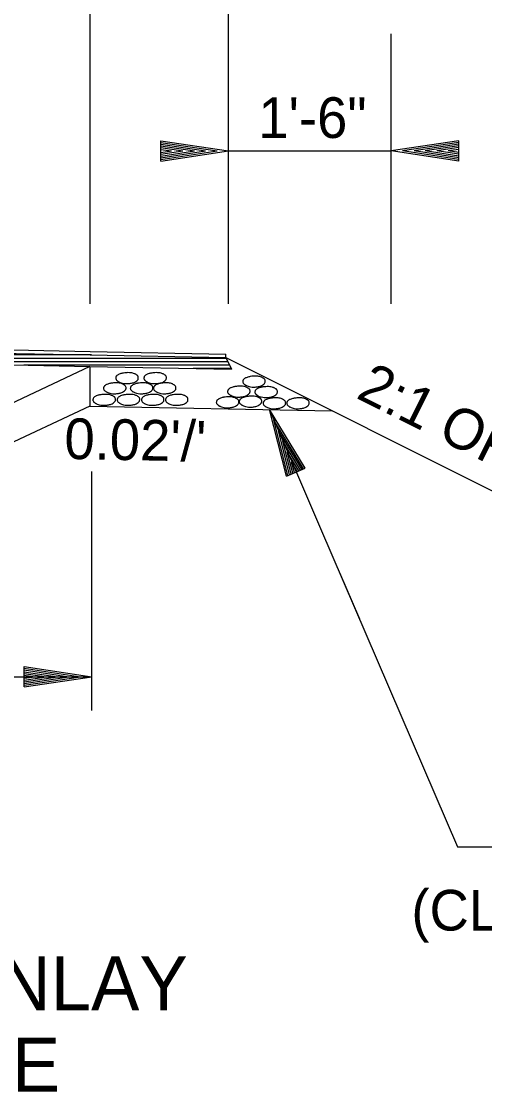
# Model space of a CAD drawing. Extents: x 2263886 to 2266026, y -3122850 to -3121850.
# Drawn here: x 2265407.19 to 2265414.02, y -3122494.29 to -3122478.48 of the extents above; entities that cross this region are included whole.
import ezdxf

# ---------------------------------------------------------------- set-up
doc = ezdxf.new("R2010")
doc.units = 0
doc.layers.add('R_Border Notes', color=7, linetype='Continuous')
doc.layers.add('R_Border Prem', color=7, linetype='Continuous')

msp = doc.modelspace()

# ---------------------------------------------------------------- linework, layer by layer
at = {"layer": 'R_Border Notes'}
for p, q in [((2265397.21, -3122483.181), (2265408.208, -3122483.401)), ((2265397.211, -3122483.13), (2265408.209, -3122483.35)), ((2265397.206, -3122483.351), (2265408.204, -3122483.571)), ((2265408.209, -3122483.35), (2265410.208, -3122483.39)), ((2265410.207, -3122483.441), (2265410.208, -3122483.39)), ((2265408.229, -3122483.402), (2265399.734, -3122483.402)), ((2265410.212, -3122483.452), (2265402.232, -3122483.452)), ((2265410.237, -3122483.502), (2265404.73, -3122483.502)), ((2265410.262, -3122483.552), (2265407.228, -3122483.552)), ((2265408.208, -3122483.401), (2265410.207, -3122483.441)), ((2265410.207, -3122483.441), (2265410.293, -3122483.613)), ((2265410.207, -3122483.441), (2265419.05, -3122487.863)), ((2265408.204, -3122483.571), (2265410.293, -3122483.613)), ((2265408.204, -3122483.571), (2265408.204, -3122484.155)), ((2265410.287, -3122483.602), (2265409.727, -3122483.602)), ((2265408.204, -3122484.155), (2265411.777, -3122484.226))]:
    msp.add_line(p, q, dxfattribs=at)
at = {"layer": 'R_Border Prem'}
for p, q in [((2265410.25, -3122482.649), (2265410.25, -3122463.3)), ((2265408.208, -3122482.649), (2265408.208, -3122469.649)), ((2265412.645, -3122482.649), (2265412.645, -3122478.661)), ((2265409.25, -3122480.242), (2265410.25, -3122480.392)), ((2265409.25, -3122480.542), (2265409.25, -3122480.242)), ((2265409.25, -3122480.267), (2265410.083, -3122480.392)), ((2265409.25, -3122480.292), (2265409.911, -3122480.392)), ((2265409.25, -3122480.317), (2265409.745, -3122480.392)), ((2265409.25, -3122480.343), (2265409.575, -3122480.392)), ((2265409.25, -3122480.368), (2265409.408, -3122480.392)), ((2265413.645, -3122480.242), (2265412.645, -3122480.392)), ((2265413.645, -3122480.267), (2265412.812, -3122480.392)), ((2265413.645, -3122480.292), (2265412.984, -3122480.392)), ((2265413.645, -3122480.317), (2265413.15, -3122480.392)), ((2265413.645, -3122480.343), (2265413.32, -3122480.392)), ((2265413.645, -3122480.368), (2265413.487, -3122480.392)), ((2265413.645, -3122480.542), (2265413.645, -3122480.242)), ((2265409.25, -3122480.542), (2265410.25, -3122480.392)), ((2265409.25, -3122480.44), (2265409.575, -3122480.392)), ((2265409.25, -3122480.491), (2265409.911, -3122480.392)), ((2265409.25, -3122480.517), (2265410.083, -3122480.392)), ((2265409.25, -3122480.466), (2265409.745, -3122480.392)), ((2265409.25, -3122480.415), (2265409.408, -3122480.392)), ((2265410.25, -3122480.392), (2265412.645, -3122480.392)), ((2265413.645, -3122480.542), (2265412.645, -3122480.392)), ((2265413.645, -3122480.517), (2265412.812, -3122480.392)), ((2265413.645, -3122480.491), (2265412.984, -3122480.392)), ((2265413.645, -3122480.466), (2265413.15, -3122480.392)), ((2265413.645, -3122480.44), (2265413.32, -3122480.392)), ((2265413.645, -3122480.415), (2265413.487, -3122480.392)), ((2265408.204, -3122483.571), (2265405.716, -3122484.743)), ((2265408.204, -3122484.155), (2265405.716, -3122485.327)), ((2265410.852, -3122484.208), (2265411.607, -3122485.962)), ((2265411.102, -3122485.188), (2265410.852, -3122484.208)), ((2265411.379, -3122485.071), (2265410.852, -3122484.208)), ((2265411.125, -3122485.178), (2265410.917, -3122484.362)), ((2265411.356, -3122485.081), (2265410.917, -3122484.362)), ((2265411.332, -3122485.091), (2265410.984, -3122484.52)), ((2265411.149, -3122485.168), (2265410.984, -3122484.52)), ((2265411.172, -3122485.158), (2265411.049, -3122484.674)), ((2265411.309, -3122485.1), (2265411.049, -3122484.674)), ((2265411.286, -3122485.11), (2265411.114, -3122484.83)), ((2265411.196, -3122485.148), (2265411.114, -3122484.83)), ((2265408.232, -3122488.649), (2265408.232, -3122485.119)), ((2265411.102, -3122485.188), (2265411.379, -3122485.071)), ((2265411.262, -3122485.12), (2265411.179, -3122484.984)), ((2265411.219, -3122485.138), (2265411.179, -3122484.984)), ((2265411.607, -3122485.962), (2265413.626, -3122490.658)), ((2265411.885, -3122486.611), (2265412.179, -3122487.294)), ((2265407.232, -3122487.999), (2265408.232, -3122488.149)), ((2265407.232, -3122488.299), (2265407.232, -3122487.999)), ((2265407.232, -3122488.024), (2265408.065, -3122488.149)), ((2265407.232, -3122488.05), (2265407.893, -3122488.149)), ((2265407.232, -3122488.075), (2265407.727, -3122488.149)), ((2265407.232, -3122488.1), (2265407.557, -3122488.149)), ((2265407.232, -3122488.126), (2265407.39, -3122488.149)), ((2265386.232, -3122488.149), (2265408.232, -3122488.149)), ((2265407.232, -3122488.299), (2265408.232, -3122488.149)), ((2265407.232, -3122488.198), (2265407.557, -3122488.149)), ((2265407.232, -3122488.249), (2265407.893, -3122488.149)), ((2265407.232, -3122488.274), (2265408.065, -3122488.149)), ((2265407.232, -3122488.224), (2265407.727, -3122488.149)), ((2265407.232, -3122488.173), (2265407.39, -3122488.149)), ((2265413.626, -3122490.658), (2265414.626, -3122490.658))]:
    msp.add_line(p, q, dxfattribs=at)
for points in [[(2265408.597, -3122483.711), (2265408.59, -3122483.722), (2265408.587, -3122483.732), (2265408.584, -3122483.745), (2265408.586, -3122483.753), (2265408.592, -3122483.766), (2265408.6, -3122483.776), (2265408.614, -3122483.787), (2265408.623, -3122483.795), (2265408.631, -3122483.798), (2265408.648, -3122483.807), (2265408.678, -3122483.816), (2265408.723, -3122483.824), (2265408.769, -3122483.824), (2265408.818, -3122483.817), (2265408.867, -3122483.801), (2265408.895, -3122483.782), (2265408.913, -3122483.762), (2265408.917, -3122483.745), (2265408.917, -3122483.73), (2265408.912, -3122483.714), (2265408.906, -3122483.706), (2265408.897, -3122483.698), (2265408.885, -3122483.691), (2265408.871, -3122483.682), (2265408.86, -3122483.678), (2265408.838, -3122483.67), (2265408.807, -3122483.665), (2265408.764, -3122483.663), (2265408.733, -3122483.665), (2265408.701, -3122483.668), (2265408.684, -3122483.672), (2265408.661, -3122483.677), (2265408.635, -3122483.686), (2265408.62, -3122483.694), (2265408.602, -3122483.707), (2265408.594, -3122483.714)], [(2265409.012, -3122483.711), (2265409.005, -3122483.722), (2265409.002, -3122483.732), (2265408.999, -3122483.745), (2265409.001, -3122483.753), (2265409.007, -3122483.766), (2265409.015, -3122483.776), (2265409.029, -3122483.787), (2265409.038, -3122483.795), (2265409.046, -3122483.798), (2265409.063, -3122483.807), (2265409.093, -3122483.816), (2265409.138, -3122483.824), (2265409.184, -3122483.824), (2265409.233, -3122483.817), (2265409.282, -3122483.801), (2265409.31, -3122483.782), (2265409.328, -3122483.762), (2265409.332, -3122483.745), (2265409.332, -3122483.73), (2265409.327, -3122483.714), (2265409.321, -3122483.706), (2265409.312, -3122483.698), (2265409.3, -3122483.691), (2265409.286, -3122483.682), (2265409.275, -3122483.678), (2265409.253, -3122483.67), (2265409.222, -3122483.665), (2265409.179, -3122483.663), (2265409.148, -3122483.665), (2265409.116, -3122483.668), (2265409.099, -3122483.672), (2265409.076, -3122483.677), (2265409.05, -3122483.686), (2265409.035, -3122483.694), (2265409.017, -3122483.707), (2265409.009, -3122483.714)], [(2265408.416, -3122483.861), (2265408.409, -3122483.872), (2265408.406, -3122483.882), (2265408.403, -3122483.895), (2265408.405, -3122483.903), (2265408.411, -3122483.916), (2265408.419, -3122483.926), (2265408.433, -3122483.937), (2265408.442, -3122483.945), (2265408.45, -3122483.948), (2265408.467, -3122483.957), (2265408.497, -3122483.966), (2265408.542, -3122483.974), (2265408.588, -3122483.974), (2265408.637, -3122483.967), (2265408.686, -3122483.951), (2265408.714, -3122483.932), (2265408.732, -3122483.912), (2265408.736, -3122483.895), (2265408.736, -3122483.88), (2265408.731, -3122483.864), (2265408.725, -3122483.856), (2265408.716, -3122483.848), (2265408.704, -3122483.841), (2265408.69, -3122483.832), (2265408.679, -3122483.828), (2265408.657, -3122483.82), (2265408.626, -3122483.815), (2265408.583, -3122483.813), (2265408.552, -3122483.815), (2265408.52, -3122483.818), (2265408.503, -3122483.822), (2265408.48, -3122483.827), (2265408.454, -3122483.836), (2265408.439, -3122483.844), (2265408.421, -3122483.857), (2265408.413, -3122483.864)], [(2265408.812, -3122483.861), (2265408.805, -3122483.872), (2265408.802, -3122483.882), (2265408.799, -3122483.895), (2265408.801, -3122483.903), (2265408.807, -3122483.916), (2265408.815, -3122483.926), (2265408.829, -3122483.937), (2265408.838, -3122483.945), (2265408.846, -3122483.948), (2265408.863, -3122483.957), (2265408.893, -3122483.966), (2265408.938, -3122483.974), (2265408.984, -3122483.974), (2265409.033, -3122483.967), (2265409.082, -3122483.951), (2265409.11, -3122483.932), (2265409.128, -3122483.912), (2265409.132, -3122483.895), (2265409.132, -3122483.88), (2265409.127, -3122483.864), (2265409.121, -3122483.856), (2265409.112, -3122483.848), (2265409.1, -3122483.841), (2265409.086, -3122483.832), (2265409.075, -3122483.828), (2265409.053, -3122483.82), (2265409.022, -3122483.815), (2265408.979, -3122483.813), (2265408.948, -3122483.815), (2265408.916, -3122483.818), (2265408.899, -3122483.822), (2265408.876, -3122483.827), (2265408.85, -3122483.836), (2265408.835, -3122483.844), (2265408.817, -3122483.857), (2265408.809, -3122483.864)], [(2265409.153, -3122483.861), (2265409.146, -3122483.872), (2265409.143, -3122483.882), (2265409.14, -3122483.895), (2265409.142, -3122483.903), (2265409.148, -3122483.916), (2265409.156, -3122483.926), (2265409.17, -3122483.937), (2265409.179, -3122483.945), (2265409.187, -3122483.948), (2265409.204, -3122483.957), (2265409.234, -3122483.966), (2265409.279, -3122483.974), (2265409.325, -3122483.974), (2265409.374, -3122483.967), (2265409.423, -3122483.951), (2265409.451, -3122483.932), (2265409.469, -3122483.912), (2265409.473, -3122483.895), (2265409.473, -3122483.88), (2265409.468, -3122483.864), (2265409.462, -3122483.856), (2265409.453, -3122483.848), (2265409.441, -3122483.841), (2265409.427, -3122483.832), (2265409.416, -3122483.828), (2265409.394, -3122483.82), (2265409.363, -3122483.815), (2265409.32, -3122483.813), (2265409.289, -3122483.815), (2265409.257, -3122483.818), (2265409.24, -3122483.822), (2265409.217, -3122483.827), (2265409.191, -3122483.836), (2265409.176, -3122483.844), (2265409.158, -3122483.857), (2265409.15, -3122483.864)], [(2265410.246, -3122483.91), (2265410.239, -3122483.921), (2265410.236, -3122483.931), (2265410.233, -3122483.944), (2265410.235, -3122483.952), (2265410.241, -3122483.965), (2265410.249, -3122483.975), (2265410.263, -3122483.986), (2265410.272, -3122483.994), (2265410.28, -3122483.997), (2265410.297, -3122484.006), (2265410.327, -3122484.015), (2265410.372, -3122484.023), (2265410.418, -3122484.023), (2265410.467, -3122484.016), (2265410.516, -3122484), (2265410.544, -3122483.981), (2265410.562, -3122483.961), (2265410.566, -3122483.944), (2265410.566, -3122483.929), (2265410.561, -3122483.913), (2265410.555, -3122483.905), (2265410.546, -3122483.897), (2265410.534, -3122483.89), (2265410.52, -3122483.881), (2265410.509, -3122483.877), (2265410.487, -3122483.869), (2265410.456, -3122483.864), (2265410.413, -3122483.862), (2265410.382, -3122483.864), (2265410.35, -3122483.867), (2265410.333, -3122483.871), (2265410.31, -3122483.876), (2265410.284, -3122483.885), (2265410.269, -3122483.893), (2265410.251, -3122483.906), (2265410.243, -3122483.913)], [(2265410.47, -3122483.762), (2265410.463, -3122483.773), (2265410.46, -3122483.783), (2265410.457, -3122483.796), (2265410.459, -3122483.804), (2265410.465, -3122483.817), (2265410.473, -3122483.827), (2265410.487, -3122483.838), (2265410.496, -3122483.846), (2265410.504, -3122483.849), (2265410.521, -3122483.858), (2265410.551, -3122483.867), (2265410.596, -3122483.875), (2265410.642, -3122483.875), (2265410.691, -3122483.868), (2265410.74, -3122483.852), (2265410.768, -3122483.833), (2265410.786, -3122483.813), (2265410.79, -3122483.796), (2265410.79, -3122483.781), (2265410.785, -3122483.765), (2265410.779, -3122483.757), (2265410.77, -3122483.749), (2265410.758, -3122483.742), (2265410.744, -3122483.733), (2265410.733, -3122483.729), (2265410.711, -3122483.721), (2265410.68, -3122483.716), (2265410.637, -3122483.714), (2265410.606, -3122483.716), (2265410.574, -3122483.719), (2265410.557, -3122483.723), (2265410.534, -3122483.728), (2265410.508, -3122483.737), (2265410.493, -3122483.745), (2265410.475, -3122483.758), (2265410.467, -3122483.765)], [(2265408.26, -3122484.031), (2265408.253, -3122484.042), (2265408.25, -3122484.052), (2265408.247, -3122484.065), (2265408.249, -3122484.073), (2265408.255, -3122484.086), (2265408.263, -3122484.096), (2265408.277, -3122484.107), (2265408.286, -3122484.115), (2265408.294, -3122484.118), (2265408.311, -3122484.127), (2265408.341, -3122484.136), (2265408.386, -3122484.144), (2265408.432, -3122484.144), (2265408.481, -3122484.137), (2265408.53, -3122484.121), (2265408.558, -3122484.102), (2265408.576, -3122484.082), (2265408.58, -3122484.065), (2265408.58, -3122484.05), (2265408.575, -3122484.034), (2265408.569, -3122484.026), (2265408.56, -3122484.018), (2265408.548, -3122484.011), (2265408.534, -3122484.002), (2265408.523, -3122483.998), (2265408.501, -3122483.99), (2265408.47, -3122483.985), (2265408.427, -3122483.983), (2265408.396, -3122483.985), (2265408.364, -3122483.988), (2265408.347, -3122483.992), (2265408.324, -3122483.997), (2265408.298, -3122484.006), (2265408.283, -3122484.014), (2265408.265, -3122484.027), (2265408.257, -3122484.034)], [(2265408.618, -3122484.031), (2265408.611, -3122484.042), (2265408.608, -3122484.052), (2265408.605, -3122484.065), (2265408.607, -3122484.073), (2265408.613, -3122484.086), (2265408.621, -3122484.096), (2265408.635, -3122484.107), (2265408.644, -3122484.115), (2265408.652, -3122484.118), (2265408.669, -3122484.127), (2265408.699, -3122484.136), (2265408.744, -3122484.144), (2265408.79, -3122484.144), (2265408.839, -3122484.137), (2265408.888, -3122484.121), (2265408.916, -3122484.102), (2265408.934, -3122484.082), (2265408.938, -3122484.065), (2265408.938, -3122484.05), (2265408.933, -3122484.034), (2265408.927, -3122484.026), (2265408.918, -3122484.018), (2265408.906, -3122484.011), (2265408.892, -3122484.002), (2265408.881, -3122483.998), (2265408.859, -3122483.99), (2265408.828, -3122483.985), (2265408.785, -3122483.983), (2265408.754, -3122483.985), (2265408.722, -3122483.988), (2265408.705, -3122483.992), (2265408.682, -3122483.997), (2265408.656, -3122484.006), (2265408.641, -3122484.014), (2265408.623, -3122484.027), (2265408.615, -3122484.034)], [(2265408.976, -3122484.031), (2265408.969, -3122484.042), (2265408.966, -3122484.052), (2265408.963, -3122484.065), (2265408.965, -3122484.073), (2265408.971, -3122484.086), (2265408.979, -3122484.096), (2265408.993, -3122484.107), (2265409.002, -3122484.115), (2265409.01, -3122484.118), (2265409.027, -3122484.127), (2265409.057, -3122484.136), (2265409.102, -3122484.144), (2265409.148, -3122484.144), (2265409.197, -3122484.137), (2265409.246, -3122484.121), (2265409.274, -3122484.102), (2265409.292, -3122484.082), (2265409.296, -3122484.065), (2265409.296, -3122484.05), (2265409.291, -3122484.034), (2265409.285, -3122484.026), (2265409.276, -3122484.018), (2265409.264, -3122484.011), (2265409.25, -3122484.002), (2265409.239, -3122483.998), (2265409.217, -3122483.99), (2265409.186, -3122483.985), (2265409.143, -3122483.983), (2265409.112, -3122483.985), (2265409.08, -3122483.988), (2265409.063, -3122483.992), (2265409.04, -3122483.997), (2265409.014, -3122484.006), (2265408.999, -3122484.014), (2265408.981, -3122484.027), (2265408.973, -3122484.034)], [(2265409.33, -3122484.031), (2265409.323, -3122484.042), (2265409.32, -3122484.052), (2265409.317, -3122484.065), (2265409.319, -3122484.073), (2265409.325, -3122484.086), (2265409.333, -3122484.096), (2265409.347, -3122484.107), (2265409.356, -3122484.115), (2265409.364, -3122484.118), (2265409.381, -3122484.127), (2265409.411, -3122484.136), (2265409.456, -3122484.144), (2265409.502, -3122484.144), (2265409.551, -3122484.137), (2265409.6, -3122484.121), (2265409.628, -3122484.102), (2265409.646, -3122484.082), (2265409.65, -3122484.065), (2265409.65, -3122484.05), (2265409.645, -3122484.034), (2265409.639, -3122484.026), (2265409.63, -3122484.018), (2265409.618, -3122484.011), (2265409.604, -3122484.002), (2265409.593, -3122483.998), (2265409.571, -3122483.99), (2265409.54, -3122483.985), (2265409.497, -3122483.983), (2265409.466, -3122483.985), (2265409.434, -3122483.988), (2265409.417, -3122483.992), (2265409.394, -3122483.997), (2265409.368, -3122484.006), (2265409.353, -3122484.014), (2265409.335, -3122484.027), (2265409.327, -3122484.034)], [(2265410.081, -3122484.068), (2265410.074, -3122484.079), (2265410.071, -3122484.089), (2265410.068, -3122484.102), (2265410.07, -3122484.11), (2265410.076, -3122484.123), (2265410.084, -3122484.133), (2265410.098, -3122484.144), (2265410.107, -3122484.152), (2265410.115, -3122484.155), (2265410.132, -3122484.164), (2265410.162, -3122484.173), (2265410.207, -3122484.181), (2265410.253, -3122484.181), (2265410.302, -3122484.174), (2265410.351, -3122484.158), (2265410.379, -3122484.139), (2265410.397, -3122484.119), (2265410.401, -3122484.102), (2265410.401, -3122484.087), (2265410.396, -3122484.071), (2265410.39, -3122484.063), (2265410.381, -3122484.055), (2265410.369, -3122484.048), (2265410.355, -3122484.039), (2265410.344, -3122484.035), (2265410.322, -3122484.027), (2265410.291, -3122484.022), (2265410.248, -3122484.02), (2265410.217, -3122484.022), (2265410.185, -3122484.025), (2265410.168, -3122484.029), (2265410.145, -3122484.034), (2265410.119, -3122484.043), (2265410.104, -3122484.051), (2265410.086, -3122484.064), (2265410.078, -3122484.071)], [(2265410.418, -3122484.058), (2265410.411, -3122484.069), (2265410.408, -3122484.079), (2265410.405, -3122484.092), (2265410.407, -3122484.1), (2265410.413, -3122484.113), (2265410.421, -3122484.123), (2265410.435, -3122484.134), (2265410.444, -3122484.142), (2265410.452, -3122484.145), (2265410.469, -3122484.154), (2265410.499, -3122484.163), (2265410.544, -3122484.171), (2265410.59, -3122484.171), (2265410.639, -3122484.164), (2265410.688, -3122484.148), (2265410.716, -3122484.129), (2265410.734, -3122484.109), (2265410.738, -3122484.092), (2265410.738, -3122484.077), (2265410.733, -3122484.061), (2265410.727, -3122484.053), (2265410.718, -3122484.045), (2265410.706, -3122484.038), (2265410.692, -3122484.029), (2265410.681, -3122484.025), (2265410.659, -3122484.017), (2265410.628, -3122484.012), (2265410.585, -3122484.01), (2265410.554, -3122484.012), (2265410.522, -3122484.015), (2265410.505, -3122484.019), (2265410.482, -3122484.024), (2265410.456, -3122484.033), (2265410.441, -3122484.041), (2265410.423, -3122484.054), (2265410.415, -3122484.061)], [(2265410.649, -3122483.917), (2265410.642, -3122483.928), (2265410.639, -3122483.938), (2265410.636, -3122483.951), (2265410.638, -3122483.959), (2265410.644, -3122483.972), (2265410.652, -3122483.982), (2265410.666, -3122483.993), (2265410.675, -3122484.001), (2265410.683, -3122484.004), (2265410.7, -3122484.013), (2265410.73, -3122484.022), (2265410.775, -3122484.03), (2265410.821, -3122484.03), (2265410.87, -3122484.023), (2265410.919, -3122484.007), (2265410.947, -3122483.988), (2265410.965, -3122483.968), (2265410.969, -3122483.951), (2265410.969, -3122483.936), (2265410.964, -3122483.92), (2265410.958, -3122483.912), (2265410.949, -3122483.904), (2265410.937, -3122483.897), (2265410.923, -3122483.888), (2265410.912, -3122483.884), (2265410.89, -3122483.876), (2265410.859, -3122483.871), (2265410.816, -3122483.869), (2265410.785, -3122483.871), (2265410.753, -3122483.874), (2265410.736, -3122483.878), (2265410.713, -3122483.883), (2265410.687, -3122483.892), (2265410.672, -3122483.9), (2265410.654, -3122483.913), (2265410.646, -3122483.92)], [(2265410.771, -3122484.082), (2265410.764, -3122484.093), (2265410.761, -3122484.103), (2265410.758, -3122484.116), (2265410.76, -3122484.124), (2265410.766, -3122484.137), (2265410.774, -3122484.147), (2265410.788, -3122484.158), (2265410.797, -3122484.166), (2265410.805, -3122484.169), (2265410.822, -3122484.178), (2265410.852, -3122484.187), (2265410.897, -3122484.195), (2265410.943, -3122484.195), (2265410.992, -3122484.188), (2265411.041, -3122484.172), (2265411.069, -3122484.153), (2265411.087, -3122484.133), (2265411.091, -3122484.116), (2265411.091, -3122484.101), (2265411.086, -3122484.085), (2265411.08, -3122484.077), (2265411.071, -3122484.069), (2265411.059, -3122484.062), (2265411.045, -3122484.053), (2265411.034, -3122484.049), (2265411.012, -3122484.041), (2265410.981, -3122484.036), (2265410.938, -3122484.034), (2265410.907, -3122484.036), (2265410.875, -3122484.039), (2265410.858, -3122484.043), (2265410.835, -3122484.048), (2265410.809, -3122484.057), (2265410.794, -3122484.065), (2265410.776, -3122484.078), (2265410.768, -3122484.085)], [(2265411.119, -3122484.082), (2265411.112, -3122484.093), (2265411.109, -3122484.103), (2265411.106, -3122484.116), (2265411.108, -3122484.124), (2265411.114, -3122484.137), (2265411.122, -3122484.147), (2265411.136, -3122484.158), (2265411.145, -3122484.166), (2265411.153, -3122484.169), (2265411.17, -3122484.178), (2265411.2, -3122484.187), (2265411.245, -3122484.195), (2265411.291, -3122484.195), (2265411.34, -3122484.188), (2265411.389, -3122484.172), (2265411.417, -3122484.153), (2265411.435, -3122484.133), (2265411.439, -3122484.116), (2265411.439, -3122484.101), (2265411.434, -3122484.085), (2265411.428, -3122484.077), (2265411.419, -3122484.069), (2265411.407, -3122484.062), (2265411.393, -3122484.053), (2265411.382, -3122484.049), (2265411.36, -3122484.041), (2265411.329, -3122484.036), (2265411.286, -3122484.034), (2265411.255, -3122484.036), (2265411.223, -3122484.039), (2265411.206, -3122484.043), (2265411.183, -3122484.048), (2265411.157, -3122484.057), (2265411.142, -3122484.065), (2265411.124, -3122484.078), (2265411.116, -3122484.085)]]:
    msp.add_spline(points, degree=3, dxfattribs=at)

# ---------------------------------------------------------------- texts
for s, height, p in [('1\'-6"', 0.6, (2265410.688, -3122480.2)), ('(CLASS 7) VAR. COMPACTED DEPTH', 0.6, (2265412.946, -3122491.895)), ('HWY. 5 SEC. 18 SHOULDER WIDENING, MILL & INLAY ', 0.8, (2265382.302, -3122493.074)), ('W/ULTRATHIN BONDED WEARING COURSE', 0.8, (2265385.3, -3122494.274))]:
    msp.add_text(s, height=height, dxfattribs=at).set_placement(p)
for s, rotation, p in [('2:1 OR FLATTER', 333.435, (2265412.111, -3122484.029)), ("0.02'/'", 358.8542, (2265407.823, -3122484.934))]:
    msp.add_text(s, height=0.6, rotation=rotation, dxfattribs=at).set_placement(p)

doc.saveas('drawing.dxf')
